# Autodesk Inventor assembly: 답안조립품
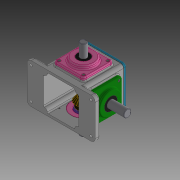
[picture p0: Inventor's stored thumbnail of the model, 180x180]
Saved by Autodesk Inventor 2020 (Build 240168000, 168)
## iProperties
Created: 2021-11
Part Number: 답안조립품
Document SubType Name: Assembly
Designer: user
Author: user
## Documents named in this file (16)
- C:\Users\user\Desktop\611112V1003\답안조립품.iam
- C:\Users\user\Desktop\611112V1003\개스킷.ipt
- C:\Users\user\Desktop\611112V1003\메인베벨기어.ipt
- C:\Users\user\Desktop\611112V1003\메인축.ipt
- C:\Users\user\Desktop\611112V1003\메인커버.ipt
- C:\Users\user\Desktop\611112V1003\베어링 6203.ipt
- C:\Users\user\Desktop\611112V1003\베어링 6204.ipt
- C:\Users\user\Desktop\611112V1003\본체.ipt
- C:\Users\user\Desktop\611112V1003\볼트 M4.ipt
- C:\Users\user\Desktop\611112V1003\상부커버.ipt
- C:\Users\user\Desktop\611112V1003\서브베벨기어.ipt
- C:\Users\user\Desktop\611112V1003\서브축.ipt
- C:\Users\user\Desktop\611112V1003\서브커버.ipt
- C:\Users\user\Desktop\611112V1003\오일 실 17 32 8.ipt
- C:\Users\user\Desktop\611112V1003\오일 실 20 35 8.ipt
- C:\Users\user\Desktop\611112V1003\키 4x4.ipt
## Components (1 placed, 1 different names)
1. 개스킷:1
